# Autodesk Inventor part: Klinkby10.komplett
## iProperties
Created: 2009-10
Part Number: Klinkby10.komplett
Document SubType Name: Modeling
Designer: TB
Mass: 6.93081 g
Surface Area: 38.3338 cm^2
Volume: 6.93081 cm^3
Density: 1 g/cm^3
Author: TB
